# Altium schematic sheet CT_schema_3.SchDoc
size 493 x 398 mm
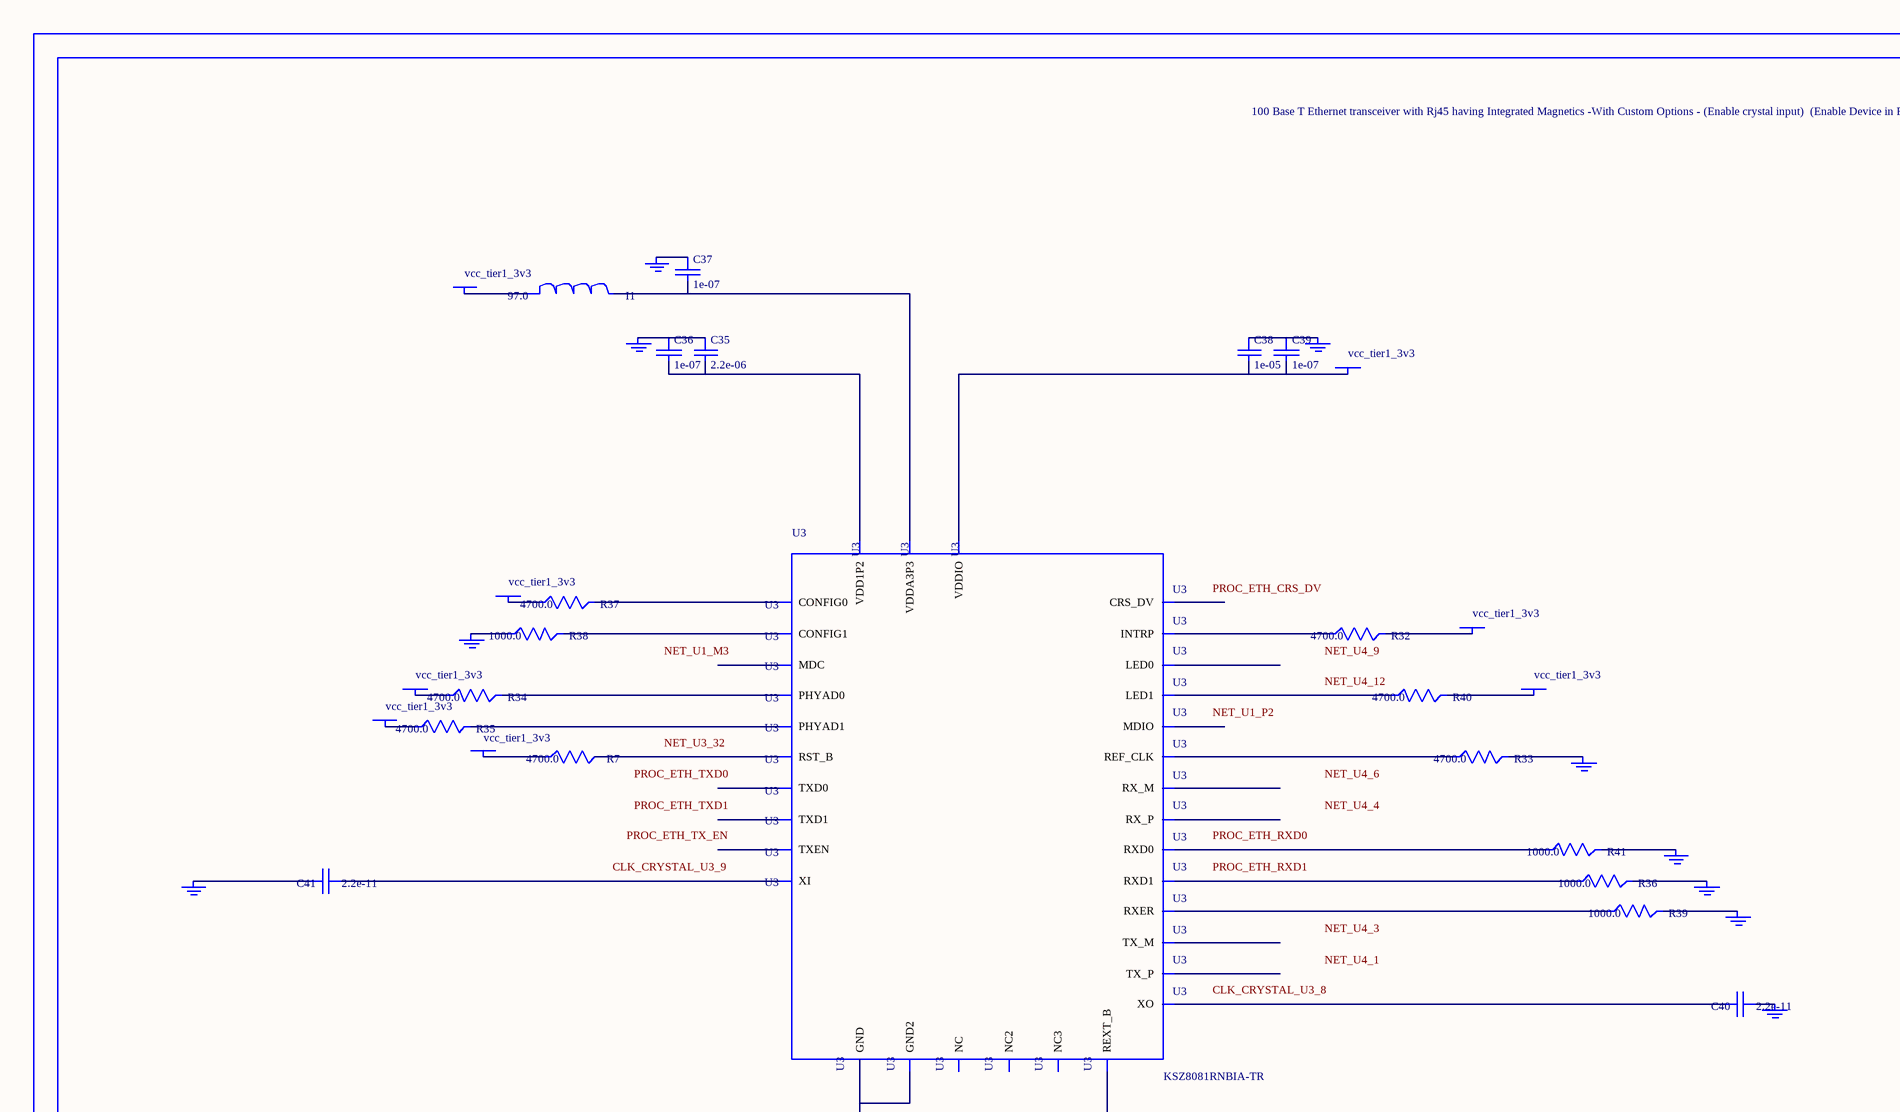
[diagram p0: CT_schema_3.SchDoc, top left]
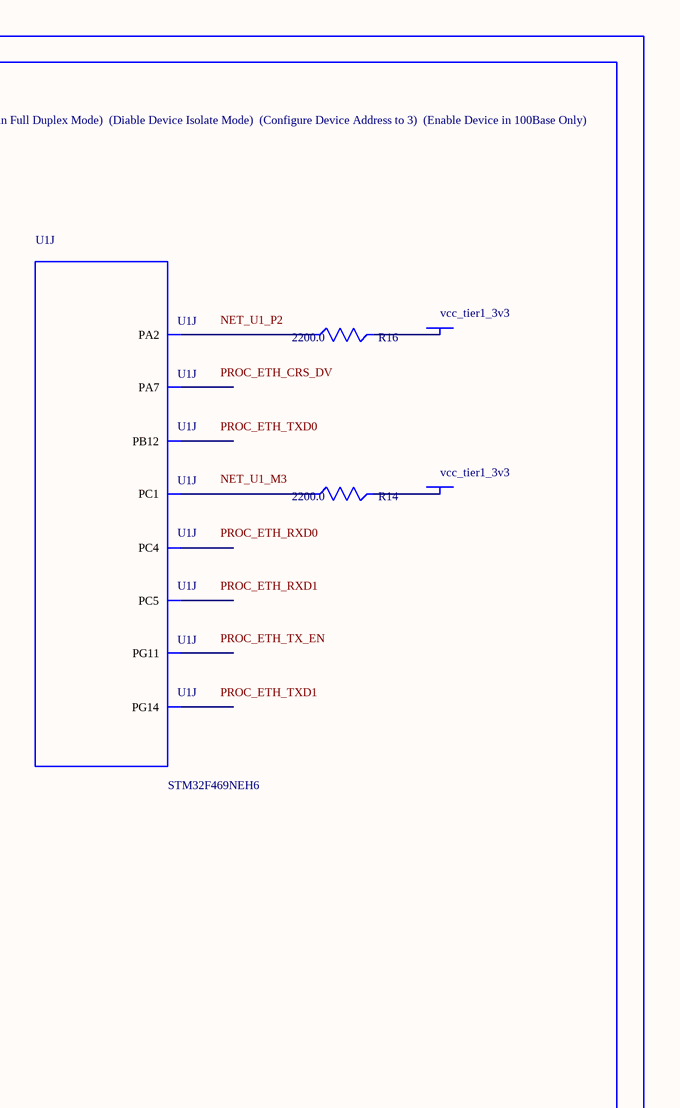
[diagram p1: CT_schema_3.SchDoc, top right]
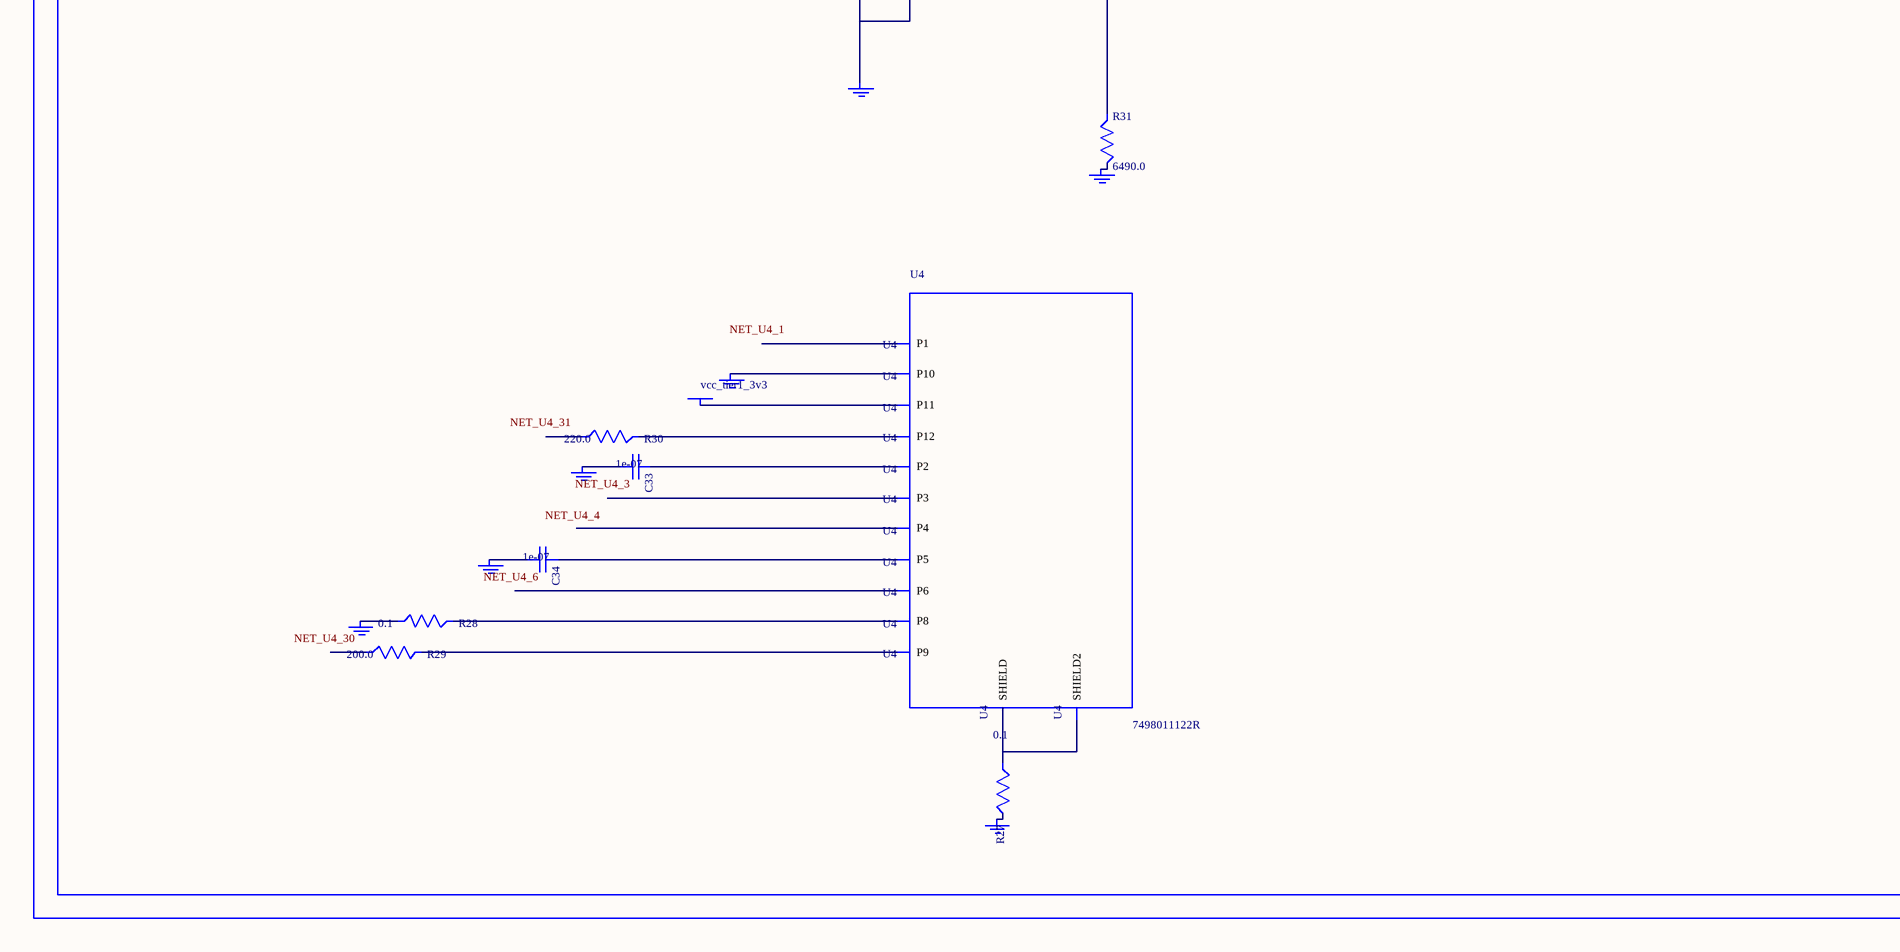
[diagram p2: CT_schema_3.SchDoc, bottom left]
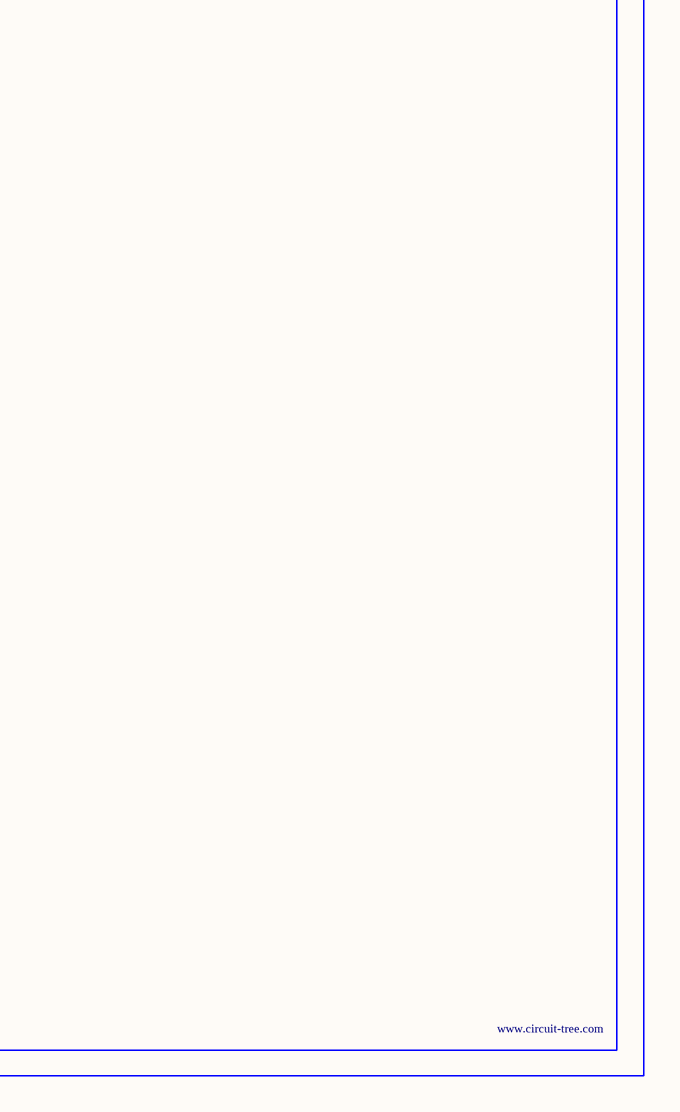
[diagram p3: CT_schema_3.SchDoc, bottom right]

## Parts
BORDER2  (no value)
C33  1e-07  [C0402]
C34  1e-07  [C0402]
C35  2.2e-06  [C0603]
C36  1e-07  [C0402]
C37  1e-07  [C0402]
C38  1e-05  [C0805]
C39  1e-07  [C0402]
C40  2.2e-11  [C0402]
C41  2.2e-11  [C0402]
GND_INSTANCE_2_0  (no value)
GND_INSTANCE_2_1  (no value)
GND_INSTANCE_2_2  (no value)
GND_INSTANCE_2_3  (no value)
GND_INSTANCE_2_4  (no value)
GND_INSTANCE_2_5  (no value)
GND_INSTANCE_2_6  (no value)
GND_INSTANCE_2_7  (no value)
GND_INSTANCE_2_8  (no value)
GND_INSTANCE_2_9  (no value)
GND_INSTANCE_2_10  (no value)
GND_INSTANCE_2_11  (no value)
GND_INSTANCE_2_12  (no value)
GND_INSTANCE_2_13  (no value)
GND_INSTANCE_2_14  (no value)
GND_INSTANCE_2_15  (no value)
GND_INSTANCE_2_16  (no value)
I1  97.0  [R0603]
POWER_INSTANCE_2_0  vcc_tier1_3v3
POWER_INSTANCE_2_1  vcc_tier1_3v3
POWER_INSTANCE_2_2  vcc_tier1_3v3
POWER_INSTANCE_2_3  vcc_tier1_3v3
POWER_INSTANCE_2_4  vcc_tier1_3v3
POWER_INSTANCE_2_5  vcc_tier1_3v3
POWER_INSTANCE_2_6  vcc_tier1_3v3
POWER_INSTANCE_2_7  vcc_tier1_3v3
POWER_INSTANCE_2_8  vcc_tier1_3v3
POWER_INSTANCE_2_9  vcc_tier1_3v3
POWER_INSTANCE_2_10  vcc_tier1_3v3
R7  4700.0  [R0603]
R14  2200.0  [R0603]
R16  2200.0  [R0603]
R27  0.1  [R0603]
R28  0.1  [R0603]
R29  200.0  [R0603]
R30  220.0  [R0603]
R31  6490.0  [R0603]
R32  4700.0  [R0603]
R33  4700.0  [R0603]
R34  4700.0  [R0603]
R35  4700.0  [R0603]
R36  1000.0  [R0603]
R37  4700.0  [R0603]
R38  1000.0  [R0603]
R39  1000.0  [R0603]
R40  4700.0  [R0603]
R41  1000.0  [R0603]
U1  STM32F469NEH6  [TFBGA216]  (part J of 17)
U3  KSZ8081RNBIA-TR  [QFN-32]
U4  7498011122R  [7498011122R]

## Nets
NetC33_1: C33.1 U4.2(P2)
NetC33_2: C33.2 GND_INSTANCE_2_12.0(GND)
NetC34_1: C34.1 U4.5(P5)
NetC34_2: C34.2 GND_INSTANCE_2_13.0(GND)
NetC35_1: C35.1 C36.1 GND_INSTANCE_2_0.0(GND)
NetC35_2: C35.2 C36.2 U3.2(VDD1P2)
NetC37_1: C37.1 GND_INSTANCE_2_1.0(GND)
NetC37_2: C37.2 I1.2 U3.3(VDDA3P3)
NetC38_1: C38.1 C39.1 GND_INSTANCE_2_7.0(GND)
NetC38_2: C38.2 C39.2 POWER_INSTANCE_2_3.0(PWR) U3.17(VDDIO)
NetC40_1: C40.1 GND_INSTANCE_2_2.0(GND)
NetC40_2: C40.2 U3.8(XO)
NetC41_1: C41.1 U3.9(XI)
NetC41_2: C41.2 GND_INSTANCE_2_3.0(GND)
NetGND_INSTANCE_2_4_0: GND_INSTANCE_2_4.0(GND) R31.2
NetGND_INSTANCE_2_5_0: GND_INSTANCE_2_5.0(GND) R36.2
NetGND_INSTANCE_2_6_0: GND_INSTANCE_2_6.0(GND) R41.2
NetGND_INSTANCE_2_8_0: GND_INSTANCE_2_8.0(GND) R33.2
NetGND_INSTANCE_2_9_0: GND_INSTANCE_2_9.0(GND) R39.2
NetGND_INSTANCE_2_10_0: GND_INSTANCE_2_10.0(GND) R38.1
NetGND_INSTANCE_2_11_0: GND_INSTANCE_2_11.0(GND) U3.1(GND) U3.EXP(GND2)
NetGND_INSTANCE_2_14_0: GND_INSTANCE_2_14.0(GND) R28.1
NetGND_INSTANCE_2_15_0: GND_INSTANCE_2_15.0(GND) U4.10(P10)
NetGND_INSTANCE_2_16_0: GND_INSTANCE_2_16.0(GND) R27.2
NetI1_1: I1.1 POWER_INSTANCE_2_0.0(PWR)
NetPOWER_INSTANCE_2_1_0: POWER_INSTANCE_2_1.0(PWR) R34.1
NetPOWER_INSTANCE_2_2_0: POWER_INSTANCE_2_2.0(PWR) R35.1
NetPOWER_INSTANCE_2_4_0: POWER_INSTANCE_2_4.0(PWR) R32.2
NetPOWER_INSTANCE_2_5_0: POWER_INSTANCE_2_5.0(PWR) R37.1
NetPOWER_INSTANCE_2_6_0: POWER_INSTANCE_2_6.0(PWR) R40.2
NetPOWER_INSTANCE_2_7_0: POWER_INSTANCE_2_7.0(PWR) R7.1
NetPOWER_INSTANCE_2_8_0: POWER_INSTANCE_2_8.0(PWR) R16.2
NetPOWER_INSTANCE_2_9_0: POWER_INSTANCE_2_9.0(PWR) R14.2
NetPOWER_INSTANCE_2_10_0: POWER_INSTANCE_2_10.0(PWR) U4.11(P11)
NetR7_2: R7.2 U3.32(RST_B)
NetR14_1: R14.1 U1.M3(PC1)
NetR16_1: R16.1 U1.P2(PA2)
NetR27_1: R27.1 U4.13(SHIELD) U4.14(SHIELD2)
NetR28_2: R28.2 U4.8(P8)
NetR29_2: R29.2 U4.9(P9)
NetR30_2: R30.2 U4.12(P12)
NetR31_1: R31.1 U3.10(REXT_B)
NetR32_1: R32.1 U3.21(INTRP)
NetR33_1: R33.1 U3.19(REF_CLK)
NetR34_2: R34.2 U3.13(PHYAD0)
NetR35_2: R35.2 U3.14(PHYAD1)
NetR36_1: R36.1 U3.15(RXD1)
NetR37_2: R37.2 U3.28(CONFIG0)
NetR38_2: R38.2 U3.29(CONFIG1)
NetR39_1: R39.1 U3.20(RXER)
NetR40_1: R40.1 U3.31(LED1)
NetR41_1: R41.1 U3.16(RXD0)

Not connected (* = marked no-connect by the designer): R29 1; R30 1; U1 A4(PG14) B8(PG11) L13(PB12) N5(PC4) P5(PC5) R3(PA7); U3 4(RX_M) 5(RX_P) 6(TX_M) 7(TX_P) 11(MDIO) 12(MDC) 18(CRS_DV) 22(NC) 23(TXEN) 24(TXD0) 25(TXD1) 26(NC2) 27(NC3) 30(LED0); U4 1(P1) 3(P3) 4(P4) 6(P6)

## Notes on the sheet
- Labels drawn without touching a wire or pin: CLK_CRYSTAL_U3_8, CLK_CRYSTAL_U3_9, NET_U1_M3, NET_U1_P2, NET_U3_32, NET_U4_1, NET_U4_3, NET_U4_4, NET_U4_6, NET_U4_9, NET_U4_12, NET_U4_30, NET_U4_31, PROC_ETH_CRS_DV, PROC_ETH_RXD0, PROC_ETH_RXD1, PROC_ETH_TX_EN, PROC_ETH_TXD0, PROC_ETH_TXD1

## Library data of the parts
BORDER2 = BORDER_PAGE2
C33 C34 C36 C37 C39 = C0402C104K3RACTU
C35 = C0603C225K8RACTU
C38 = C0805C106K8RACTU
C40 C41 = C0402C220K3RAC
GND_INSTANCE_2_0-GND_INSTANCE_2_16 = GND
I1 = I1
POWER_INSTANCE_2_0-POWER_INSTANCE_2_10 = PWR
R7 R32-R35 R37 R40 = RC0603JR-074K7L
R14 R16 = RC0603JR-072K2L
R27 R28 = ERJ-3RSFR10V
R29 = RC0603JR-07200RL
R30 = RC0603JR-07220RL
R31 = ERJ-3EKF6491V
R36 R38 R39 R41 = RC0603JR-071KL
